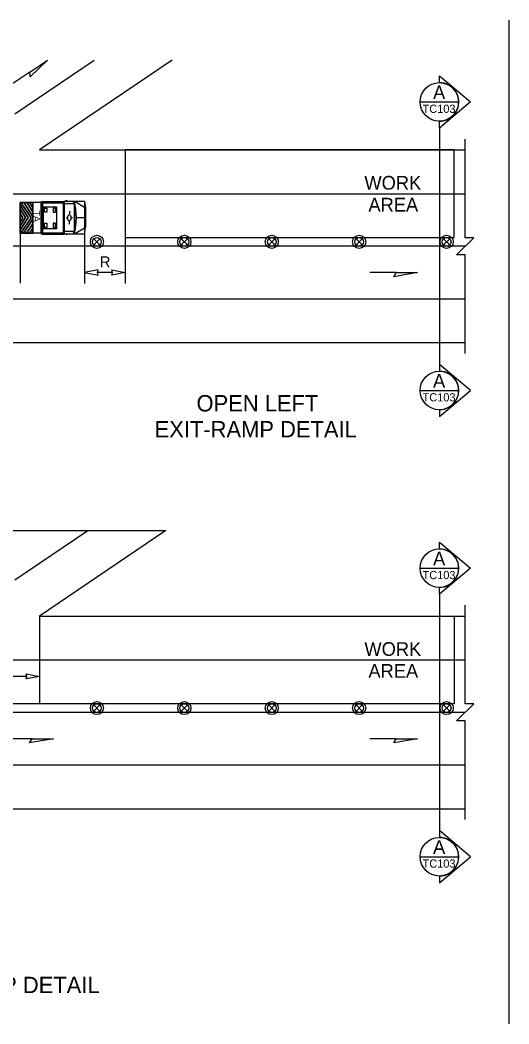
# Model space of a CAD drawing. Extents: x 99999 to 100116, y 99995 to 100013.
# Drawn here: x 100084.3 to 100087.88, y 100001.58 to 100008.92 of the extents above; entities that cross this region are included whole.
import ezdxf

# ---------------------------------------------------------------- set-up
doc = ezdxf.new("R2010")
doc.units = 0
for name, color, linetype in [('RD_MK_LineEdgeYellow', 7, 'Continuous'), ('RD_MK_LineLane', 7, 'Continuous'), ('SH_DE_DetailHeading2Text', 7, 'Continuous'), ('SH_TI_WZSectionCut', 7, 'Continuous'), ('TR_WZ_TrafficSafetyDrum', 7, 'Continuous'), ('TR_WZ_TransportableAttenuator', 7, 'Continuous'), ('TR_WZ_WorkAreaLabel', 7, 'Continuous'), ('TR_WZ_WorkZoneDetails', 7, 'Continuous'), ('TR_WZ_WorkZoneTextCurrent', 7, 'Continuous')]:
    doc.layers.add(name, color=color, linetype=linetype)

msp = doc.modelspace()

# ---------------------------------------------------------------- linework, layer by layer
at = {"layer": 'RD_MK_LineEdgeYellow'}
for p, q in [((100084.2592, 100008.2329), (100084.8392, 100008.626)), ((100084.4388, 100007.648), (100087.555, 100007.648)), ((100080.32, 100006.88), (100087.555, 100006.88)), ((100084.2592, 100004.8228), (100084.7935, 100005.1849)), ((100084.4388, 100004.238), (100087.555, 100004.238)), ((100080.32, 100003.47), (100087.555, 100003.47))]:
    msp.add_line(p, q, dxfattribs=at)
at = {"layer": 'RD_MK_LineLane'}
for points in [[(100087.555, 100007.264), (100080.32, 100007.264)], [(100087.555, 100003.854), (100080.32, 100003.854)]]:
    msp.add_lwpolyline(points, dxfattribs=at)
at = {"layer": 'SH_TI_WZSectionCut'}
for p, q in [((100087.3657, 100008.4604), (100087.3657, 100008.5103)), ((100087.3657, 100008.5103), (100087.5938, 100008.3192)), ((100087.5938, 100008.3192), (100087.3657, 100008.128)), ((100087.3657, 100008.128), (100087.3657, 100008.1779)), ((100087.3657, 100008.128), (100087.3657, 100006.4)), ((100087.3657, 100006.4), (100087.3657, 100006.3501)), ((100087.5939, 100006.2089), (100087.3657, 100006.4)), ((100087.3657, 100006.0178), (100087.5939, 100006.2089)), ((100087.3657, 100006.0677), (100087.3657, 100006.0178)), ((100087.3657, 100005.0503), (100087.3657, 100005.1002)), ((100087.3657, 100005.1002), (100087.5938, 100004.9091)), ((100087.5938, 100004.9091), (100087.3657, 100004.718)), ((100087.3657, 100004.718), (100087.3657, 100004.7679)), ((100087.3657, 100004.718), (100087.3657, 100002.99)), ((100087.3657, 100002.99), (100087.3657, 100002.94)), ((100087.5939, 100002.7988), (100087.3657, 100002.99)), ((100087.3657, 100002.6077), (100087.5939, 100002.7988)), ((100087.3657, 100002.6576), (100087.3657, 100002.6077))]:
    msp.add_line(p, q, dxfattribs=at)
for points in [[(100087.2245, 100008.3192), (100087.5069, 100008.3192)], [(100087.2245, 100006.2089), (100087.5069, 100006.2089)], [(100087.2245, 100004.9091), (100087.5069, 100004.9091)], [(100087.2245, 100002.7988), (100087.5069, 100002.7988)]]:
    msp.add_lwpolyline(points, dxfattribs=at)
for centre in [(100087.3657, 100008.3192), (100087.3657, 100006.2089), (100087.3657, 100004.9091), (100087.3657, 100002.7988)]:
    msp.add_circle(centre, 0.1412, dxfattribs=at)
for centre in [(100087.3657, 100008.3192), (100087.3657, 100006.2089), (100087.3657, 100004.9091), (100087.3657, 100002.7988)]:
    msp.add_arc(centre, 0.1412, 269.99779, 90.00221, dxfattribs=at)
at = {"layer": 'TR_WZ_TrafficSafetyDrum'}
for p, q in [((100084.8363, 100007.2734), (100084.8815, 100007.3186)), ((100084.8815, 100007.2734), (100084.8363, 100007.3186)), ((100085.4763, 100007.2734), (100085.5215, 100007.3186)), ((100085.5215, 100007.2734), (100085.4763, 100007.3186)), ((100086.1163, 100007.2734), (100086.1615, 100007.3186)), ((100086.1615, 100007.2734), (100086.1163, 100007.3186)), ((100086.7563, 100007.2734), (100086.8015, 100007.3186)), ((100086.8015, 100007.2734), (100086.7563, 100007.3186)), ((100087.3963, 100007.2734), (100087.4415, 100007.3186)), ((100087.4415, 100007.2734), (100087.3963, 100007.3186)), ((100084.8363, 100003.8633), (100084.8815, 100003.9086)), ((100084.8815, 100003.8633), (100084.8363, 100003.9086)), ((100085.4763, 100003.8633), (100085.5215, 100003.9086)), ((100085.5215, 100003.8633), (100085.4763, 100003.9086)), ((100086.1163, 100003.8633), (100086.1615, 100003.9086)), ((100086.1615, 100003.8633), (100086.1163, 100003.9086)), ((100086.7563, 100003.8633), (100086.8015, 100003.9086)), ((100086.8015, 100003.8633), (100086.7563, 100003.9086)), ((100087.3963, 100003.8633), (100087.4415, 100003.9086)), ((100087.4415, 100003.8633), (100087.3963, 100003.9086))]:
    msp.add_line(p, q, dxfattribs=at)
for centre, radius in [((100084.8589, 100007.296), 0.048), ((100084.8589, 100007.296), 0.048), ((100084.8589, 100007.296), 0.032), ((100085.4989, 100007.296), 0.048), ((100085.4989, 100007.296), 0.048), ((100085.4989, 100007.296), 0.032), ((100086.1389, 100007.296), 0.048), ((100086.1389, 100007.296), 0.048), ((100086.1389, 100007.296), 0.032), ((100086.7789, 100007.296), 0.048), ((100086.7789, 100007.296), 0.048), ((100086.7789, 100007.296), 0.032), ((100087.4189, 100007.296), 0.048), ((100087.4189, 100007.296), 0.048), ((100087.4189, 100007.296), 0.032), ((100084.8589, 100003.886), 0.048), ((100084.8589, 100003.886), 0.048), ((100084.8589, 100003.886), 0.032), ((100085.4989, 100003.886), 0.048), ((100085.4989, 100003.886), 0.048), ((100085.4989, 100003.886), 0.032), ((100086.1389, 100003.886), 0.048), ((100086.1389, 100003.886), 0.048), ((100086.1389, 100003.886), 0.032), ((100086.7789, 100003.886), 0.048), ((100086.7789, 100003.886), 0.048), ((100086.7789, 100003.886), 0.032), ((100087.4189, 100003.886), 0.048), ((100087.4189, 100003.886), 0.048), ((100087.4189, 100003.886), 0.032)]:
    msp.add_circle(centre, radius, dxfattribs=at)
at = {"layer": 'TR_WZ_TransportableAttenuator'}
for p, q in [((100084.3775, 100007.4722), (100084.3026, 100007.5849)), ((100084.3026, 100007.5849), (100084.323, 100007.5849)), ((100084.3026, 100007.5849), (100084.3775, 100007.4722)), ((100084.323, 100007.5849), (100084.3026, 100007.5849)), ((100084.323, 100007.5849), (100084.3907, 100007.4822)), ((100084.3907, 100007.4822), (100084.323, 100007.5849)), ((100084.3907, 100007.5154), (100084.3451, 100007.5849)), ((100084.3451, 100007.5849), (100084.3655, 100007.5849)), ((100084.3655, 100007.5849), (100084.3451, 100007.5849)), ((100084.3451, 100007.5849), (100084.3907, 100007.5154)), ((100084.3655, 100007.5849), (100084.3907, 100007.5467)), ((100084.3907, 100007.5467), (100084.3655, 100007.5849)), ((100084.3907, 100007.3596), (100084.3907, 100007.5849)), ((100084.4551, 100007.5849), (100084.3907, 100007.5849)), ((100084.4511, 100007.5881), (100084.4546, 100007.5881)), ((100084.4546, 100007.5881), (100084.4546, 100007.3559)), ((100084.4551, 100007.592), (100084.6177, 100007.592)), ((100084.4551, 100007.592), (100084.4551, 100007.352)), ((100084.4551, 100007.5845), (100084.4551, 100007.3596)), ((100084.4598, 100007.5825), (100084.4598, 100007.3616)), ((100084.4598, 100007.5825), (100084.6131, 100007.5825)), ((100084.6131, 100007.5825), (100084.6131, 100007.3616)), ((100084.6177, 100007.592), (100084.6177, 100007.352)), ((100084.6199, 100007.592), (100084.6199, 100007.352)), ((100084.7691, 100007.592), (100084.6199, 100007.592)), ((100084.6402, 100007.5954), (100084.6312, 100007.5954)), ((100084.6931, 100007.592), (100084.6836, 100007.5734)), ((100084.6931, 100007.592), (100084.6931, 100007.352)), ((100084.6944, 100007.592), (100084.6944, 100007.352)), ((100084.7691, 100007.5481), (100084.6944, 100007.592)), ((100084.7691, 100007.592), (100084.7691, 100007.352)), ((100084.7691, 100007.592), (100084.7764, 100007.5436)), ((100084.2964, 100007.5635), (100084.3565, 100007.4729)), ((100084.2964, 100007.5343), (100084.2964, 100007.5635)), ((100084.3565, 100007.4729), (100084.2964, 100007.5635)), ((100084.2964, 100007.5635), (100084.2964, 100007.5343)), ((100084.3372, 100007.4732), (100084.2964, 100007.5343)), ((100084.2964, 100007.5343), (100084.3372, 100007.4732)), ((100084.3907, 100007.5467), (100084.3907, 100007.5154)), ((100084.3907, 100007.5154), (100084.3907, 100007.5467)), ((100084.4475, 100007.5808), (100084.4475, 100007.3633)), ((100084.6931, 100007.5734), (100084.6199, 100007.5734)), ((100084.6573, 100007.5196), (100084.6573, 100007.5002)), ((100084.7764, 100007.5436), (100084.7764, 100007.4005)), ((100084.2964, 100007.5034), (100084.3173, 100007.4724)), ((100084.2964, 100007.441), (100084.2964, 100007.5034)), ((100084.3173, 100007.4724), (100084.2964, 100007.5034)), ((100084.2964, 100007.5034), (100084.2964, 100007.441)), ((100084.2964, 100007.4118), (100084.3372, 100007.4732)), ((100084.3372, 100007.4732), (100084.2964, 100007.4118)), ((100084.3565, 100007.4729), (100084.2964, 100007.3824)), ((100084.2964, 100007.3824), (100084.3565, 100007.4729)), ((100084.3173, 100007.4724), (100084.2964, 100007.441)), ((100084.2964, 100007.441), (100084.3173, 100007.4724)), ((100084.3025, 100007.3594), (100084.3775, 100007.4722)), ((100084.3775, 100007.4722), (100084.3025, 100007.3594)), ((100084.3907, 100007.4621), (100084.3226, 100007.3594)), ((100084.3226, 100007.3594), (100084.3907, 100007.4621)), ((100084.3907, 100007.4822), (100084.3907, 100007.4621)), ((100084.3907, 100007.4621), (100084.3907, 100007.4822)), ((100084.4475, 100007.4889), (100084.4546, 100007.4844)), ((100084.4475, 100007.4551), (100084.4546, 100007.4596)), ((100084.4494, 100007.472), (100084.4527, 100007.472)), ((100084.4511, 100007.4754), (100084.4511, 100007.4686)), ((100084.6335, 100007.4722), (100084.6434, 100007.4721)), ((100084.6462, 100007.4716), (100084.6462, 100007.4716)), ((100084.6573, 100007.4245), (100084.6573, 100007.4438)), ((100084.6811, 100007.4722), (100084.6711, 100007.4721)), ((100084.7691, 100007.472), (100084.7091, 100007.472)), ((100084.2964, 100007.3824), (100084.2964, 100007.4118)), ((100084.2964, 100007.4118), (100084.2964, 100007.3824)), ((100084.3446, 100007.3594), (100084.3907, 100007.4289)), ((100084.3907, 100007.4289), (100084.3446, 100007.3594)), ((100084.3907, 100007.3958), (100084.3662, 100007.3594)), ((100084.3662, 100007.3594), (100084.3907, 100007.3958)), ((100084.3907, 100007.4289), (100084.3907, 100007.3958)), ((100084.3907, 100007.3958), (100084.3907, 100007.4289)), ((100084.4598, 100007.3616), (100084.6131, 100007.3616)), ((100084.6931, 100007.3706), (100084.6199, 100007.3706)), ((100084.6852, 100007.3706), (100084.6931, 100007.352)), ((100084.7691, 100007.3959), (100084.6944, 100007.352)), ((100084.7691, 100007.352), (100084.7764, 100007.4005)), ((100084.3226, 100007.3594), (100084.3025, 100007.3594)), ((100084.3025, 100007.3594), (100084.3226, 100007.3594)), ((100084.3662, 100007.3594), (100084.3446, 100007.3594)), ((100084.3446, 100007.3594), (100084.3662, 100007.3594)), ((100084.4551, 100007.3596), (100084.3907, 100007.3596)), ((100084.4511, 100007.3559), (100084.4546, 100007.3559)), ((100084.4551, 100007.352), (100084.6177, 100007.352)), ((100084.7691, 100007.352), (100084.6199, 100007.352)), ((100084.6402, 100007.3487), (100084.6312, 100007.3487))]:
    msp.add_line(p, q, dxfattribs=at)
for points in [[(100084.3907, 100007.3594), (100084.2964, 100007.3594), (100084.2964, 100007.5849), (100084.3907, 100007.5849)], [(100084.4678, 100007.552), (100084.5638, 100007.552), (100084.5638, 100007.392), (100084.4678, 100007.392)], [(100084.4758, 100007.542), (100084.4918, 100007.542), (100084.4918, 100007.512), (100084.4758, 100007.512)], [(100084.5558, 100007.542), (100084.5398, 100007.542), (100084.5398, 100007.512), (100084.5558, 100007.512)], [(100084.4758, 100007.432), (100084.4918, 100007.432), (100084.4918, 100007.402), (100084.4758, 100007.402)], [(100084.5558, 100007.432), (100084.5398, 100007.432), (100084.5398, 100007.402), (100084.5558, 100007.402)]]:
    msp.add_lwpolyline(points, close=True, dxfattribs=at)
msp.add_lwpolyline([(100084.3907, 100007.5849), (100084.2964, 100007.5849), (100084.2964, 100007.3594), (100084.3907, 100007.3596)], dxfattribs=at)
for centre, major_axis, start_param, end_param in [((100084.4511, 100007.5807), (0, 0.00732), 6.283185, 7.853982), ((100084.5878, 100007.472), (0, 0.2519), 4.215852, 5.209111), ((100084.4511, 100007.3633), (0, -0.00732), 4.712389, 6.283185)]:
    msp.add_ellipse(centre, major_axis=major_axis, ratio=0.481608, start_param=start_param, end_param=end_param, dxfattribs=at)
for centre, major_axis in [((100084.4511, 100007.472), (0, -0.00338)), ((100084.6573, 100007.472), (0, -0.0231))]:
    msp.add_ellipse(centre, major_axis=major_axis, ratio=0.481608, dxfattribs=at)
at = {"layer": 'TR_WZ_WorkZoneDetails'}
for p, q in [((100087.875, 100008.9181), (100087.875, 100001.5759)), ((100085.409, 100008.626), (100084.4388, 100007.968)), ((100084.3668, 100008.5378), (100084.2071, 100008.4295)), ((100084.4388, 100007.968), (100087.555, 100007.968)), ((100083.3963, 100007.648), (100084.4388, 100007.648)), ((100084.2964, 100007.3594), (100084.2964, 100006.9947)), ((100084.7691, 100007.352), (100084.7691, 100006.9906)), ((100085.0668, 100007.328), (100085.0668, 100006.9906)), ((100084.973, 100007.072), (100084.8628, 100007.072)), ((100087.0492, 100007.072), (100086.8563, 100007.072)), ((100080.32, 100006.56), (100087.555, 100006.56)), ((100085.3633, 100005.1849), (100084.4388, 100004.558)), ((100084.4388, 100004.558), (100084.4388, 100003.918)), ((100084.4388, 100004.558), (100087.555, 100004.558)), ((100083.3963, 100004.238), (100084.4388, 100004.238)), ((100084.3451, 100004.118), (100081.9752, 100004.118)), ((100084.3844, 100003.662), (100084.1915, 100003.662)), ((100087.0492, 100003.662), (100086.8563, 100003.662)), ((100080.32, 100003.15), (100087.555, 100003.15))]:
    msp.add_line(p, q, dxfattribs=at)
for points in [[(100084.497, 100008.626), (100084.3694, 100008.5022), (100084.3668, 100008.5378)], [(100085.0668, 100007.968), (100085.0668, 100007.328), (100087.475, 100007.328), (100087.475, 100007.968)], [(100084.7691, 100007.072), (100084.8674, 100007.0528), (100084.8628, 100007.072), (100084.8674, 100007.0913)], [(100085.0668, 100007.072), (100084.9685, 100007.0528), (100084.973, 100007.072), (100084.9685, 100007.0913)], [(100087.2065, 100007.072), (100087.0314, 100007.0412), (100087.0492, 100007.072)], [(100080.4, 100004.558), (100082.9559, 100004.558), (100083.8809, 100005.1849), (100085.3633, 100005.1849), (100084.4388, 100004.558), (100085.8504, 100004.558), (100087.475, 100004.558), (100087.475, 100003.918), (100080.4, 100003.918)], [(100084.4388, 100004.118), (100084.3405, 100004.0987), (100084.3451, 100004.118), (100084.3405, 100004.1372)], [(100084.5416, 100003.662), (100084.3665, 100003.6311), (100084.3844, 100003.662)], [(100087.2065, 100003.662), (100087.0314, 100003.6311), (100087.0492, 100003.662)]]:
    msp.add_lwpolyline(points, close=True, dxfattribs=at)
for points in [[(100087.555, 100006.48), (100087.555, 100007.2021), (100087.491, 100007.2021), (100087.619, 100007.326), (100087.555, 100007.326), (100087.555, 100008.048)], [(100087.555, 100003.07), (100087.555, 100003.792), (100087.491, 100003.792), (100087.619, 100003.9159), (100087.555, 100003.9159), (100087.555, 100004.638)]]:
    msp.add_lwpolyline(points, dxfattribs=at)

# ---------------------------------------------------------------- texts
at = {"layer": 'SH_DE_DetailHeading2Text'}
for s, p in [('OPEN LEFT', (100085.5881, 100006.0554)), ('EXIT-RAMP DETAIL', (100085.2814, 100005.8654)), ('CLOSED LEFT EXIT-RAMP DETAIL', (100082.2571, 100001.8009))]:
    msp.add_text(s, height=0.12, rotation=360, dxfattribs=at).set_placement(p)
at = {"layer": 'SH_TI_WZSectionCut'}
for s, height, rotation, p in [('A', 0.1, 0.00995, (100087.3195, 100008.3398)), ('TC103', 0.06, 360, (100087.243, 100008.2392)), ('A', 0.1, 0.00995, (100087.3195, 100006.2295)), ('TC103', 0.06, 360, (100087.243, 100006.1289)), ('A', 0.1, 0.00995, (100087.3195, 100004.9297)), ('TC103', 0.06, 360, (100087.243, 100004.8291)), ('A', 0.1, 0.00995, (100087.3195, 100002.8195)), ('TC103', 0.06, 360, (100087.243, 100002.7188))]:
    msp.add_text(s, height=height, rotation=rotation, dxfattribs=at).set_placement(p)
at = {"layer": 'TR_WZ_TransportableAttenuator'}
msp.add_text('TA', height=0.048, rotation=270, dxfattribs=at).set_placement((100084.3951, 100007.5246))
at = {"layer": 'TR_WZ_WorkAreaLabel'}
for s, p in [('WORK', (100086.8169, 100007.678)), ('AREA', (100086.8465, 100007.518)), ('WORK', (100086.8169, 100004.268)), ('AREA', (100086.8465, 100004.108))]:
    msp.add_text(s, height=0.1, dxfattribs=at).set_placement(p)
at = {"layer": 'TR_WZ_WorkZoneTextCurrent'}
msp.add_text('R', height=0.08, dxfattribs=at).set_placement((100084.8804, 100007.11))

doc.saveas('drawing.dxf')
